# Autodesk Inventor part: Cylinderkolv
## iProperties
Created: 2001-12
Part Number: Cylinderkolv
Material: SS2172
Document SubType Name: Modeling
Designer: Tobben
Control State: 0
Master: False
Checked Out: False
Shininess: 64.0
Length Units: 11269
Angle Units: 11279
Time Units: 11290
Mass Units: 11283
Length Display Precision: 3
Angle Display Precision: 2
Compacted: True
Density: 0.0
Volumn: 0.0
Area: 0.0
PropertySet Name: Model Information
Author: Tobben
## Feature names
1. Revolution1
